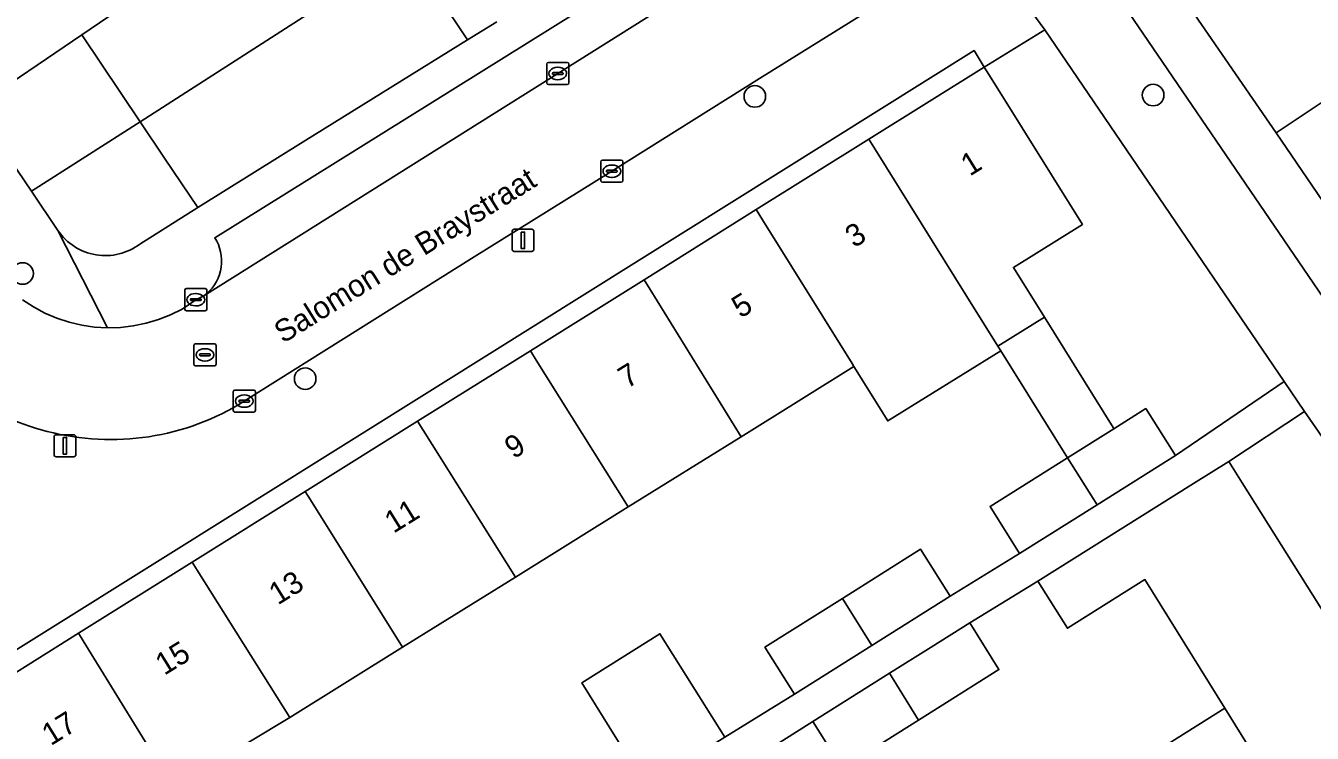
# Model space of a CAD drawing. Extents: x 159664 to 160323, y 385312 to 386115.
# Drawn here: x 160072.6 to 160130.8, y 385907.3 to 385939.3 of the extents above; entities that cross this region are included whole.
import ezdxf

# ---------------------------------------------------------------- set-up
doc = ezdxf.new("R2010")
doc.units = 0
for name, color, linetype in [('IMGEO_Boom', 7, 'Continuous'), ('IMGEO_Erf', 7, 'Continuous'), ('IMGEO_Fietspad_gesloten', 7, 'Continuous'), ('IMGEO_Groenvoorziening', 7, 'Continuous'), ('IMGEO_Kolk', 7, 'Continuous'), ('IMGEO_Lichtmast', 7, 'Continuous'), ('IMGEO_Openbare_ruimte_label', 7, 'Continuous'), ('IMGEO_Pand', 7, 'Continuous'), ('IMGEO_Pand_nummerreeks', 7, 'Continuous'), ('IMGEO_Parkeervlak_open', 7, 'Continuous'), ('IMGEO_Rijbaan_lokaal_open', 7, 'Continuous'), ('IMGEO_Rioolput', 7, 'Continuous'), ('IMGEO_Verkeerseiland_groen', 7, 'Continuous'), ('IMGEO_Voetpad_open', 7, 'Continuous')]:
    doc.layers.add(name, color=color, linetype=linetype)

msp = doc.modelspace()

# ---------------------------------------------------------------- linework, layer by layer
at = {"layer": 'IMGEO_Boom'}
for centre in [(160105.579, 385936.148), (160123.593, 385936.208), (160072.459, 385928.136), (160085.241, 385923.378)]:
    msp.add_circle(centre, 0.489, dxfattribs=at)
at = {"layer": 'IMGEO_Erf'}
for points in [[(160118.692, 385939.162), (160115.949, 385937.476), (160116.264, 385936.971), (160120.395, 385930.354), (160117.271, 385928.411), (160118.676, 385926.154), (160121.778, 385921.17), (160121.812, 385921.116), (160123.261, 385922.027), (160124.6, 385919.896), (160129.522, 385923.245)], [(160115.492, 385938.223), (160091.367, 385923.112), (160069.413, 385909.399), (160069.893, 385908.671), (160074.992, 385911.86), (160080.13, 385915.074), (160085.247, 385918.274), (160090.327, 385921.451), (160095.429, 385924.642), (160100.567, 385927.855), (160105.639, 385931.027), (160110.739, 385934.217), (160115.949, 385937.476)], [(160126.839, 385908.47), (160123.221, 385914.292), (160119.716, 385912.09), (160118.382, 385914.213), (160115.296, 385912.328), (160116.62, 385910.22), (160112.979, 385907.932), (160109.521, 385905.76), (160108.197, 385907.868), (160106.387, 385906.731), (160112.564, 385896.901), (160117.776, 385900.176), (160122.877, 385903.38), (160121.717, 385905.252)]]:
    msp.add_lwpolyline(points, close=True, dxfattribs=at)
for points in [[(160099.342, 385907.073), (160097.759, 385909.621), (160101.284, 385911.84), (160104.221, 385907.166), (160107.37, 385909.108), (160106.032, 385911.239), (160109.536, 385913.441), (160113.076, 385915.665), (160114.415, 385913.534), (160117.555, 385915.47), (160116.217, 385917.601), (160119.724, 385919.804), (160116.701, 385924.642), (160111.59, 385921.466), (160110.059, 385923.926), (160104.956, 385920.752), (160099.853, 385917.579), (160094.748, 385914.404), (160089.644, 385911.23), (160084.541, 385908.057), (160079.289, 385904.884)], [(160131.05, 385921), (160130.445, 385921.889), (160127.016, 385919.637), (160127.624, 385918.669), (160133.168, 385909.846), (160137.262, 385903.33), (160132.048, 385900.054), (160126.96, 385896.858), (160121.871, 385893.66), (160116.658, 385890.385), (160118.445, 385887.533), (160139.28, 385900.589), (160141.001, 385901.665)]]:
    msp.add_lwpolyline(points, dxfattribs=at)
at = {"layer": 'IMGEO_Fietspad_gesloten'}
for points in [[(160019.602, 386088.23), (160021.107, 386086.925), (160023.91, 386084.079), (160027.277, 386080.36), (160034.647, 386069.613), (160036.811, 386066.205), (160038.328, 386063.633), (160039.436, 386061.981), (160045.694, 386052.822), (160114.376, 385951.813), (160120.736, 385942.537), (160142.935, 385909.961), (160144.932, 385911.316), (160142.024, 385915.62), (160129.151, 385934.503)], [(160129.151, 385934.503), (160122.71, 385943.882), (160116.725, 385952.645), (160107.048, 385966.948), (160106.703, 385967.457), (160102.65, 385973.412), (160102.316, 385973.903), (160098.145, 385979.992), (160097.151, 385981.487), (160088.665, 385993.953), (160088.353, 385994.453), (160083.105, 386002.104), (160081.757, 386004.091), (160078.702, 386008.561), (160078.214, 386009.324), (160072.955, 386016.982), (160072.299, 386017.991), (160068.359, 386023.773), (160067.183, 386025.518), (160061.154, 386034.366), (160060.642, 386035.125), (160059.222, 386037.252)]]:
    msp.add_lwpolyline(points, dxfattribs=at)
at = {"layer": 'IMGEO_Groenvoorziening'}
for points in [[(160087.04, 385947.028), (160085.243, 385949.537), (160077.36, 385944.203), (160077.22, 385944.421), (160070.856, 385940.099), (160071.008, 385939.886), (160068.546, 385938.209), (160070.287, 385935.642), (160075.136, 385938.938)], [(160077.783, 385934.997), (160089.873, 385942.783), (160088.809, 385944.378), (160087.04, 385947.028), (160075.136, 385938.938)], [(160080.39, 385931.114), (160085.269, 385934.169), (160092.589, 385938.713), (160089.873, 385942.783), (160077.783, 385934.997), (160078.884, 385933.357)], [(160075.136, 385938.938), (160070.287, 385935.642), (160072.858, 385931.853), (160077.783, 385934.997)]]:
    msp.add_lwpolyline(points, close=True, dxfattribs=at)
for points in [[(160078.884, 385933.357), (160077.783, 385934.997), (160072.858, 385931.853), (160074.061, 385930.08)], [(160077.764, 385929.469), (160080.39, 385931.114), (160078.884, 385933.357)]]:
    msp.add_lwpolyline(points, dxfattribs=at)
msp.add_arc((160076.202, 385931.531), 2.587, 214.1268, 307.13428, dxfattribs=at)
at = {"layer": 'IMGEO_Kolk'}
for p, q in [((160096.164, 385936.757), (160096.164, 385937.609)), ((160096.239, 385937.683), (160097.091, 385937.683)), ((160096.652, 385937.463), (160096.677, 385937.463)), ((160097.165, 385937.609), (160097.165, 385936.757)), ((160096.423, 385937.177), (160096.423, 385937.189)), ((160096.861, 385937.14), (160096.463, 385937.14)), ((160096.466, 385937.226), (160096.864, 385937.226)), ((160096.675, 385936.903), (160096.65, 385936.903)), ((160096.907, 385937.189), (160096.907, 385937.177)), ((160097.091, 385936.683), (160096.239, 385936.683)), ((160098.612, 385932.337), (160098.612, 385933.189)), ((160098.687, 385933.263), (160099.539, 385933.263)), ((160098.914, 385932.806), (160099.312, 385932.806)), ((160099.1, 385933.043), (160099.125, 385933.043)), ((160099.613, 385933.189), (160099.613, 385932.337)), ((160099.539, 385932.263), (160098.687, 385932.263)), ((160098.871, 385932.757), (160098.871, 385932.769)), ((160099.309, 385932.72), (160098.911, 385932.72)), ((160099.123, 385932.483), (160099.098, 385932.483)), ((160099.355, 385932.769), (160099.355, 385932.757)), ((160079.793, 385926.525), (160079.793, 385927.377)), ((160079.868, 385927.451), (160080.72, 385927.451)), ((160080.052, 385926.945), (160080.052, 385926.957)), ((160080.095, 385926.994), (160080.493, 385926.994)), ((160080.281, 385927.231), (160080.306, 385927.231)), ((160080.536, 385926.957), (160080.536, 385926.945)), ((160080.794, 385927.377), (160080.794, 385926.525)), ((160080.72, 385926.451), (160079.868, 385926.451)), ((160080.49, 385926.908), (160080.092, 385926.908)), ((160080.304, 385926.671), (160080.279, 385926.671)), ((160081.986, 385921.938), (160081.986, 385922.79)), ((160082.061, 385922.864), (160082.913, 385922.864)), ((160082.245, 385922.358), (160082.245, 385922.37)), ((160082.683, 385922.321), (160082.285, 385922.321)), ((160082.288, 385922.407), (160082.686, 385922.407)), ((160082.474, 385922.644), (160082.499, 385922.644)), ((160082.729, 385922.37), (160082.729, 385922.358)), ((160082.987, 385922.79), (160082.987, 385921.938)), ((160082.913, 385921.864), (160082.061, 385921.864)), ((160082.497, 385922.084), (160082.472, 385922.084))]:
    msp.add_line(p, q, dxfattribs=at)
for points in [[(160096.164, 385936.757), (160096.164, 385937.609)], [(160096.239, 385937.683), (160097.091, 385937.683)], [(160097.165, 385937.609), (160097.165, 385936.757)], [(160097.091, 385936.683), (160096.239, 385936.683)], [(160098.612, 385932.337), (160098.612, 385933.189)], [(160098.687, 385933.263), (160099.539, 385933.263)], [(160099.613, 385933.189), (160099.613, 385932.337)], [(160099.539, 385932.263), (160098.687, 385932.263)], [(160079.793, 385926.525), (160079.793, 385927.377)], [(160079.868, 385927.451), (160080.72, 385927.451)], [(160080.794, 385927.377), (160080.794, 385926.525)], [(160080.72, 385926.451), (160079.868, 385926.451)], [(160081.986, 385921.938), (160081.986, 385922.79)], [(160082.061, 385922.864), (160082.913, 385922.864)], [(160082.987, 385922.79), (160082.987, 385921.938)], [(160082.913, 385921.864), (160082.061, 385921.864)]]:
    msp.add_lwpolyline(points, dxfattribs=at)
for centre, radius, start, end in [((160096.241, 385937.607), 0.0765, 91.55205, 178.44795), ((160096.241, 385937.607), 0.0765, 91.55205, 178.44795), ((160097.089, 385937.607), 0.0765, 1.55205, 88.44795), ((160097.089, 385937.607), 0.0765, 1.55205, 88.44795), ((160096.463, 385937.186), 0.0403, 85.87752, 175.75265), ((160096.46, 385937.176), 0.0366, 178.93798, 274.71019), ((160096.864, 385937.183), 0.043, 264.86636, 352.45326), ((160096.868, 385937.188), 0.0386, 1.73085, 96.63898), ((160096.241, 385936.759), 0.0765, 181.55205, 268.44795), ((160096.241, 385936.759), 0.0765, 181.55205, 268.44795), ((160097.089, 385936.759), 0.0765, 271.55205, 358.44795), ((160097.089, 385936.759), 0.0765, 271.55205, 358.44795), ((160098.689, 385933.187), 0.0765, 91.55205, 178.44795), ((160098.689, 385933.187), 0.0765, 91.55205, 178.44795), ((160098.911, 385932.766), 0.0403, 85.87752, 175.75265), ((160099.316, 385932.768), 0.0386, 1.73085, 96.63898), ((160099.537, 385933.187), 0.0765, 1.55205, 88.44795), ((160099.537, 385933.187), 0.0765, 1.55205, 88.44795), ((160098.689, 385932.339), 0.0765, 181.55205, 268.44795), ((160098.689, 385932.339), 0.0765, 181.55205, 268.44795), ((160098.908, 385932.756), 0.0366, 178.93798, 274.71019), ((160099.312, 385932.763), 0.043, 264.86636, 352.45326), ((160099.537, 385932.339), 0.0765, 271.55205, 358.44795), ((160099.537, 385932.339), 0.0765, 271.55205, 358.44795), ((160079.87, 385927.375), 0.0765, 91.55205, 178.44795), ((160079.87, 385927.375), 0.0765, 91.55205, 178.44795), ((160080.092, 385926.954), 0.0403, 85.87752, 175.75265), ((160080.497, 385926.956), 0.0386, 1.73085, 96.63898), ((160080.718, 385927.375), 0.0765, 1.55205, 88.44795), ((160080.718, 385927.375), 0.0765, 1.55205, 88.44795), ((160079.87, 385926.527), 0.0765, 181.55205, 268.44795), ((160079.87, 385926.527), 0.0765, 181.55205, 268.44795), ((160080.089, 385926.944), 0.0366, 178.93798, 274.71019), ((160080.493, 385926.951), 0.043, 264.86636, 352.45326), ((160080.718, 385926.527), 0.0765, 271.55205, 358.44795), ((160080.718, 385926.527), 0.0765, 271.55205, 358.44795), ((160082.063, 385922.788), 0.0765, 91.55205, 178.44795), ((160082.063, 385922.788), 0.0765, 91.55205, 178.44795), ((160082.285, 385922.367), 0.0403, 85.87752, 175.75265), ((160082.282, 385922.357), 0.0366, 178.93798, 274.71019), ((160082.686, 385922.364), 0.043, 264.86636, 352.45326), ((160082.69, 385922.369), 0.0386, 1.73085, 96.63898), ((160082.911, 385922.788), 0.0765, 1.55205, 88.44795), ((160082.911, 385922.788), 0.0765, 1.55205, 88.44795), ((160082.063, 385921.94), 0.0765, 181.55205, 268.44795), ((160082.063, 385921.94), 0.0765, 181.55205, 268.44795), ((160082.911, 385921.94), 0.0765, 271.55205, 358.44795), ((160082.911, 385921.94), 0.0765, 271.55205, 358.44795)]:
    msp.add_arc(centre, radius, start, end, dxfattribs=at)
for centre, major_axis, ratio, start_param, end_param in [((160096.651, 385937.183), (-0.387, 0.002), 0.722429, 4.712389, 7.853982), ((160096.676, 385937.183), (-0.39, 0.002), 0.717154, 1.570796, 4.712389), ((160099.099, 385932.763), (-0.387, 0.002), 0.722429, 4.712389, 7.853982), ((160099.124, 385932.763), (-0.39, 0.002), 0.717154, 1.570796, 4.712389), ((160080.28, 385926.951), (-0.387, 0.002), 0.722429, 4.712389, 7.853982), ((160080.305, 385926.951), (-0.39, 0.002), 0.717154, 1.570796, 4.712389), ((160082.473, 385922.364), (-0.387, 0.002), 0.722429, 4.712389, 7.853982), ((160082.498, 385922.364), (-0.39, 0.002), 0.717154, 1.570796, 4.712389)]:
    msp.add_ellipse(centre, major_axis=major_axis, ratio=ratio, start_param=start_param, end_param=end_param, dxfattribs=at)
at = {"layer": 'IMGEO_Lichtmast'}
for p, q in [((160094.597, 385929.236), (160094.597, 385930.036)), ((160094.597, 385930.036), (160094.597, 385929.236)), ((160094.697, 385930.136), (160095.487, 385930.136)), ((160095.487, 385930.136), (160094.697, 385930.136)), ((160095.587, 385930.036), (160095.587, 385929.236)), ((160095.587, 385929.236), (160095.587, 385930.036)), ((160095.487, 385929.136), (160094.697, 385929.136)), ((160094.697, 385929.136), (160095.487, 385929.136)), ((160073.881, 385919.943), (160073.881, 385920.743)), ((160073.881, 385920.743), (160073.881, 385919.943)), ((160073.981, 385920.843), (160074.771, 385920.843)), ((160074.771, 385920.843), (160073.981, 385920.843)), ((160074.871, 385920.743), (160074.871, 385919.943)), ((160074.871, 385919.943), (160074.871, 385920.743)), ((160074.771, 385919.843), (160073.981, 385919.843)), ((160073.981, 385919.843), (160074.771, 385919.843))]:
    msp.add_line(p, q, dxfattribs=at)
for points in [[(160095.017, 385930.011), (160095.167, 385930.011), (160095.167, 385929.261), (160095.017, 385929.261), (160095.017, 385930.011)], [(160074.301, 385920.718), (160074.451, 385920.718), (160074.451, 385919.968), (160074.301, 385919.968), (160074.301, 385920.718)]]:
    msp.add_lwpolyline(points, dxfattribs=at)
for centre, start, end in [((160094.697, 385930.036), 90, 180), ((160094.697, 385930.036), 90, 180), ((160095.487, 385930.036), 0, 90), ((160095.487, 385930.036), 360, 90), ((160094.697, 385929.236), 180, 270), ((160094.697, 385929.236), 180, 270), ((160095.487, 385929.236), 270, 0), ((160095.487, 385929.236), 270, 0), ((160073.981, 385920.743), 90, 180), ((160073.981, 385920.743), 90, 180), ((160074.771, 385920.743), 0, 90), ((160074.771, 385920.743), 360, 90), ((160073.981, 385919.943), 180, 270), ((160073.981, 385919.943), 180, 270), ((160074.771, 385919.943), 270, 0), ((160074.771, 385919.943), 270, 0)]:
    msp.add_arc(centre, 0.1, start, end, dxfattribs=at)
at = {"layer": 'IMGEO_Pand'}
for points in [[(160115.164, 385927.1), (160116.573, 385924.847), (160118.676, 385926.154), (160117.271, 385928.411), (160120.395, 385930.354), (160116.264, 385936.971), (160115.949, 385937.476), (160110.739, 385934.217), (160111.04, 385933.733)], [(160111.04, 385933.733), (160110.739, 385934.217), (160105.639, 385931.027), (160105.928, 385930.563), (160109.974, 385924.063), (160110.059, 385923.926), (160111.59, 385921.466), (160116.701, 385924.642), (160116.573, 385924.847), (160115.164, 385927.1)], [(160105.639, 385931.027), (160100.567, 385927.855), (160100.841, 385927.411), (160104.956, 385920.752), (160110.059, 385923.926), (160109.974, 385924.063), (160105.928, 385930.563)], [(160099.853, 385917.579), (160104.956, 385920.752), (160100.841, 385927.411), (160100.567, 385927.855), (160095.429, 385924.642), (160095.694, 385924.22)], [(160118.676, 385926.154), (160116.573, 385924.847), (160116.701, 385924.642), (160119.724, 385919.804), (160121.812, 385921.116), (160121.778, 385921.17)], [(160090.579, 385921.049), (160094.748, 385914.404), (160099.853, 385917.579), (160095.694, 385924.22), (160095.429, 385924.642), (160090.327, 385921.451)], [(160124.6, 385919.896), (160123.261, 385922.027), (160121.812, 385921.116), (160119.724, 385919.804), (160121.057, 385917.67)], [(160090.327, 385921.451), (160085.247, 385918.274), (160085.485, 385917.892), (160089.644, 385911.23), (160094.748, 385914.404), (160090.579, 385921.049)], [(160119.724, 385919.804), (160116.217, 385917.601), (160117.555, 385915.47), (160121.057, 385917.67)], [(160133.168, 385909.846), (160127.624, 385918.669), (160127.016, 385919.637), (160125.418, 385918.633), (160118.382, 385914.213), (160119.716, 385912.09), (160123.221, 385914.292), (160126.839, 385908.47), (160132.048, 385900.054), (160137.262, 385903.33)], [(160084.541, 385908.057), (160089.644, 385911.23), (160085.485, 385917.892), (160085.247, 385918.274), (160080.13, 385915.074), (160080.357, 385914.713)], [(160114.415, 385913.534), (160113.076, 385915.665), (160109.536, 385913.441), (160110.872, 385911.308)], [(160080.357, 385914.713), (160080.13, 385915.074), (160074.992, 385911.86), (160075.203, 385911.518), (160079.289, 385904.884), (160084.541, 385908.057)], [(160106.032, 385911.239), (160107.37, 385909.108), (160110.872, 385911.308), (160109.536, 385913.441)], [(160075.203, 385911.518), (160074.992, 385911.86), (160069.893, 385908.671), (160070.091, 385908.35), (160074.183, 385901.71), (160074.315, 385901.792), (160075.692, 385899.577), (160080.657, 385902.663), (160079.289, 385904.884)], [(160104.221, 385907.166), (160101.284, 385911.84), (160097.759, 385909.621), (160099.342, 385907.073), (160100.678, 385904.94)], [(160116.62, 385910.22), (160115.296, 385912.328), (160113.559, 385911.237), (160111.669, 385910.05), (160112.979, 385907.932)], [(160108.197, 385907.868), (160109.521, 385905.76), (160112.979, 385907.932), (160111.669, 385910.05)], [(160126.839, 385908.47), (160121.717, 385905.252), (160122.877, 385903.38), (160126.96, 385896.858), (160132.048, 385900.054)]]:
    msp.add_lwpolyline(points, close=True, dxfattribs=at)
at = {"layer": 'IMGEO_Parkeervlak_open'}
msp.add_lwpolyline([(160099.681, 385941.308), (160081.153, 385929.755), (160081.24, 385929.604), (160081.314, 385929.447), (160081.373, 385929.283), (160081.417, 385929.115), (160081.446, 385928.944), (160081.46, 385928.771), (160081.459, 385928.597), (160081.442, 385928.424), (160081.409, 385928.254), (160081.362, 385928.086), (160081.299, 385927.924), (160081.223, 385927.768), (160081.133, 385927.619), (160081.03, 385927.479), (160080.915, 385927.349), (160080.789, 385927.23), (160080.653, 385927.122), (160101.327, 385940.109)], dxfattribs=at)
at = {"layer": 'IMGEO_Rijbaan_lokaal_open'}
for points in [[(160112.905, 385947.28), (160112.455, 385946.969), (160110.899, 385945.992), (160109.757, 385945.335), (160101.327, 385940.109), (160080.653, 385927.122), (160080.294, 385926.951), (160079.675, 385926.524), (160079.15, 385926.263), (160078.605, 385926.049), (160078.043, 385925.882), (160077.468, 385925.765), (160076.886, 385925.697), (160076.3, 385925.68), (160075.714, 385925.714), (160075.134, 385925.799), (160074.564, 385925.933), (160074.007, 385926.116), (160073.467, 385926.346), (160072.95, 385926.622), (160072.459, 385926.942)], [(160082.487, 385922.364), (160092.77, 385928.808), (160099.113, 385932.763), (160105.791, 385936.954), (160115.757, 385943.169)], [(160131.332, 385935.953), (160129.151, 385934.503), (160142.024, 385915.62), (160144.063, 385917.026), (160143.81, 385917.351), (160131.868, 385934.922), (160131.672, 385935.211)]]:
    msp.add_lwpolyline(points, dxfattribs=at)
for centre, radius, start, end in [((160076.579, 385932.658), 12.046, 213.8264, 255.54391), ((160076.45, 385931.95), 11.328, 255.28309, 302.20248)]:
    msp.add_arc(centre, radius, start, end, dxfattribs=at)
at = {"layer": 'IMGEO_Rioolput'}
for p, q in [((160080.208, 385924.029), (160080.208, 385924.881)), ((160080.283, 385924.955), (160081.135, 385924.955)), ((160080.696, 385924.735), (160080.721, 385924.735)), ((160081.209, 385924.881), (160081.209, 385924.029)), ((160080.467, 385924.449), (160080.467, 385924.461)), ((160080.905, 385924.412), (160080.507, 385924.412)), ((160080.51, 385924.498), (160080.908, 385924.498)), ((160080.719, 385924.175), (160080.694, 385924.175)), ((160080.951, 385924.461), (160080.951, 385924.449)), ((160081.135, 385923.955), (160080.283, 385923.955))]:
    msp.add_line(p, q, dxfattribs=at)
for points in [[(160080.208, 385924.029), (160080.208, 385924.881)], [(160080.283, 385924.955), (160081.135, 385924.955)], [(160081.209, 385924.881), (160081.209, 385924.029)], [(160081.135, 385923.955), (160080.283, 385923.955)]]:
    msp.add_lwpolyline(points, dxfattribs=at)
for centre, radius, start, end in [((160080.285, 385924.879), 0.0765, 91.55205, 178.44795), ((160080.285, 385924.879), 0.0765, 91.55205, 178.44795), ((160081.133, 385924.879), 0.0765, 1.55205, 88.44795), ((160081.133, 385924.879), 0.0765, 1.55205, 88.44795), ((160080.507, 385924.458), 0.0403, 85.87752, 175.75265), ((160080.504, 385924.448), 0.0366, 178.93798, 274.71019), ((160080.908, 385924.455), 0.043, 264.86636, 352.45326), ((160080.912, 385924.46), 0.0386, 1.73085, 96.63898), ((160080.285, 385924.031), 0.0765, 181.55205, 268.44795), ((160080.285, 385924.031), 0.0765, 181.55205, 268.44795), ((160081.133, 385924.031), 0.0765, 271.55205, 358.44795), ((160081.133, 385924.031), 0.0765, 271.55205, 358.44795)]:
    msp.add_arc(centre, radius, start, end, dxfattribs=at)
for centre, major_axis, ratio, start_param, end_param in [((160080.695, 385924.455), (-0.387, 0.002), 0.722429, 4.712389, 7.853982), ((160080.72, 385924.455), (-0.39, 0.002), 0.717154, 1.570796, 4.712389)]:
    msp.add_ellipse(centre, major_axis=major_axis, ratio=ratio, start_param=start_param, end_param=end_param, dxfattribs=at)
at = {"layer": 'IMGEO_Verkeerseiland_groen'}
msp.add_lwpolyline([(160122.71, 385943.882), (160129.151, 385934.503), (160131.332, 385935.953)], dxfattribs=at)
at = {"layer": 'IMGEO_Voetpad_open'}
for points in [[(160003.096, 386030.288), (160000.172, 386034.211), (160000, 386034.437), (159996.585, 386038.952), (159993.737, 386036.877), (159989.606, 386033.897), (159990.855, 386032.064), (160000, 386018.644), (160012.705, 386000), (160014.692, 385997.067), (160015.814, 385995.41), (160049.629, 385945.494), (160050.759, 385943.825), (160071.141, 385913.737), (160067.916, 385911.581), (160069.413, 385909.399), (160091.367, 385923.112)], [(160091.367, 385923.112), (160115.492, 385938.223), (160115.949, 385937.476), (160118.692, 385939.162), (160115.757, 385943.169), (160105.791, 385936.954), (160099.113, 385932.763), (160092.77, 385928.808), (160082.487, 385922.364)], [(160089.873, 385942.783), (160092.589, 385938.713), (160093.915, 385939.526)], [(160115.757, 385943.169), (160118.692, 385939.162), (160129.522, 385923.245), (160130.445, 385921.889), (160131.05, 385921), (160141.886, 385905.073), (160145.749, 385899.752), (160146.494, 385900.365)], [(160147.03, 385903.951), (160142.935, 385909.961), (160120.736, 385942.537)], [(160074.061, 385930.08), (160076.3, 385925.68), (160076.886, 385925.697), (160077.468, 385925.765), (160078.043, 385925.882), (160078.605, 385926.049), (160079.15, 385926.263), (160079.675, 385926.524), (160080.294, 385926.951), (160080.653, 385927.122), (160080.789, 385927.23), (160080.915, 385927.349), (160081.03, 385927.479), (160081.133, 385927.619), (160081.223, 385927.768), (160081.299, 385927.924), (160081.362, 385928.086), (160081.409, 385928.254), (160081.442, 385928.424), (160081.459, 385928.597), (160081.46, 385928.771), (160081.446, 385928.944), (160081.417, 385929.115), (160081.373, 385929.283), (160081.314, 385929.447), (160081.24, 385929.604), (160081.153, 385929.755), (160099.681, 385941.308)], [(160093.915, 385939.526), (160092.589, 385938.713), (160085.269, 385934.169), (160080.39, 385931.114), (160077.764, 385929.469)], [(160072.459, 385926.942), (160072.95, 385926.622), (160073.467, 385926.346), (160074.007, 385926.116), (160074.564, 385925.933), (160075.134, 385925.799), (160075.714, 385925.714), (160076.3, 385925.68), (160074.061, 385930.08), (160072.858, 385931.853), (160070.287, 385935.642)], [(160106.387, 385906.731), (160108.197, 385907.868), (160111.669, 385910.05), (160113.559, 385911.237), (160115.296, 385912.328), (160118.382, 385914.213), (160125.418, 385918.633), (160127.016, 385919.637), (160130.445, 385921.889), (160129.522, 385923.245), (160124.6, 385919.896), (160121.057, 385917.67), (160117.555, 385915.47), (160114.415, 385913.534), (160110.872, 385911.308), (160107.37, 385909.108), (160104.221, 385907.166)]]:
    msp.add_lwpolyline(points, dxfattribs=at)
for centre, radius, start, end in [((160076.202, 385931.531), 2.587, 214.1268, 307.13428), ((160076.579, 385932.658), 12.046, 213.8264, 255.54391), ((160076.45, 385931.95), 11.328, 255.28309, 302.20248)]:
    msp.add_arc(centre, radius, start, end, dxfattribs=at)

# ---------------------------------------------------------------- texts
at = {"layer": 'IMGEO_Openbare_ruimte_label'}
msp.add_text('Salomon de Braystraat', height=1, rotation=31.87782, dxfattribs=at).set_placement((160084.24, 385924.95))
at = {"layer": 'IMGEO_Pand_nummerreeks'}
for s, rotation, p in [('1', 31.79314, (160115.3, 385932.514)), ('3', 31.79343, (160110.068, 385929.271)), ('5', 31.79343, (160104.933, 385926.088)), ('7', 31.79314, (160099.799, 385922.905)), ('9', 31.79314, (160094.664, 385919.723)), ('11', 31.79314, (160089.235, 385916.358)), ('13', 31.79314, (160084.004, 385913.115)), ('15', 31.79343, (160078.869, 385909.932)), ('17', 31.79343, (160073.734, 385906.75))]:
    msp.add_text(s, height=1, rotation=rotation, dxfattribs=at).set_placement(p)

doc.saveas('drawing.dxf')
